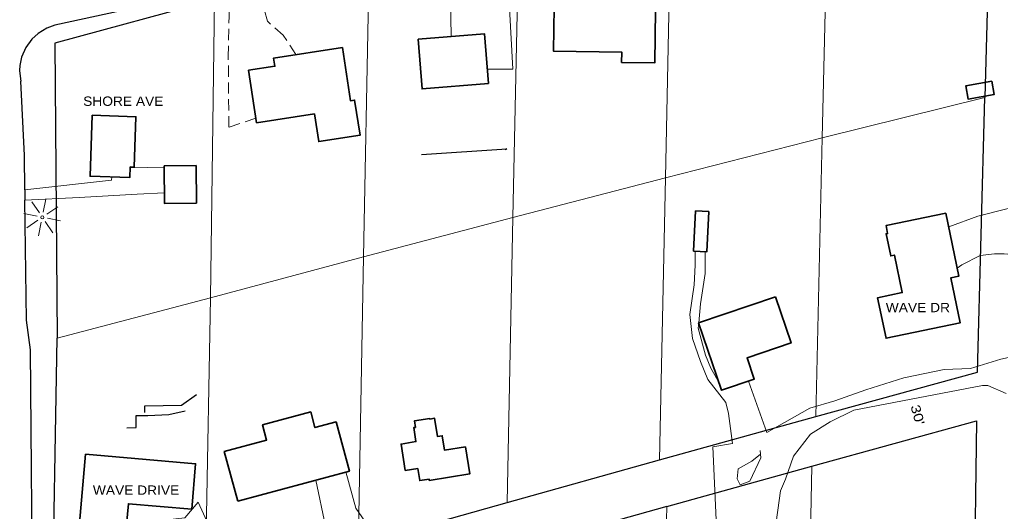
# Model space of a CAD drawing. Extents: x -861682 to -858969, y -1797841 to -1795153.
# Drawn here: x -860979 to -860350, y -1796083 to -1795768 of the extents above; entities that cross this region are included whole.
import ezdxf

# ---------------------------------------------------------------- set-up
doc = ezdxf.new("R2010")
doc.units = 0
doc.header["$LTSCALE"] = 2.4
doc.linetypes.add('MEDIUM_DASHED', pattern=[4.5, 3, -1.5])
for name, color, linetype, lineweight in [('10', 7, 'Continuous', 25), ('11', 7, 'Continuous', 13), ('12', 7, 'Continuous', 35), ('14', 7, 'Continuous', 25), ('17', 7, 'Continuous', 13), ('30', 7, 'Continuous', 13), ('42', 7, 'Continuous', 25), ('46', 7, 'Continuous', 13)]:
    doc.layers.add(name, color=color, linetype=linetype, lineweight=lineweight)
doc.layers.add('43', color=7, linetype='Continuous')

msp = doc.modelspace()

# ---------------------------------------------------------------- linework, layer by layer
at = {"layer": '10'}
for p, q in [((-860848.348, -1795747.62), (-860956.549, -1795771.257)), ((-860975.85, -1795876.828), (-860975.763, -1795883.427))]:
    msp.add_line(p, q, dxfattribs=at)
for points in [[(-860956.549, -1795771.257), (-860961.734, -1795773.101), (-860967.383, -1795776.511), (-860971.43, -1795780.239), (-860975.292, -1795785.589), (-860977.895, -1795791.653), (-860979.011, -1795797.041), (-860979.202, -1795800.339), (-860979.151, -1795802.184), (-860978.447, -1795807.129)], [(-860975.85, -1795876.828), (-860976.141, -1795854.84), (-860978.447, -1795807.129)], [(-860943.044, -1796154.171), (-860970.659, -1796157.721), (-860972.218, -1795979.333), (-860974.746, -1795960.452), (-860975.763, -1795883.427)]]:
    msp.add_lwpolyline(points, dxfattribs=at)
at = {"layer": '11'}
for p, q in [((-860702.361, -1795778.376), (-860703.253, -1795717.798)), ((-860886.521, -1795862.194), (-860908.271, -1795862.625)), ((-860504.025, -1796044.003), (-860503.778, -1796046.269))]:
    msp.add_line(p, q, dxfattribs=at)
for points in [[(-860679.135, -1795799.453), (-860662.826, -1795799.409), (-860664.822, -1795760.201), (-860679.57, -1795748.988), (-860683.051, -1795713.758)], [(-860920.125, -1795868.5), (-860920.237, -1795870.656), (-860975.85, -1795876.828)], [(-860886.377, -1795878.653), (-860903.856, -1795879.492), (-860940.935, -1795881.706), (-860975.763, -1795883.427)], [(-860382.998, -1795900.616), (-860364.271, -1795893.679), (-860344.937, -1795888.785), (-860335.906, -1795891.78)], [(-860545.785, -1795916.111), (-860545.707, -1795925.039), (-860546.305, -1795937.804), (-860549.216, -1795956.8), (-860547.423, -1795972.076), (-860542.331, -1795986.918), (-860537.504, -1795998.455), (-860526.033, -1796013.241), (-860524.246, -1796020.353), (-860521.787, -1796039.432), (-860534.291, -1796041.668), (-860531.924, -1796097.784)], [(-860539.402, -1795916.407), (-860539.28, -1795930.417), (-860542.231, -1795949.929), (-860543.384, -1795962.078), (-860543.72, -1795965.618), (-860539.024, -1795982.91), (-860535.703, -1795991.27), (-860530.382, -1796000.69)], [(-860377.503, -1795927.042), (-860374.63, -1795924.961), (-860362.868, -1795918.951), (-860353.662, -1795917.925), (-860347.518, -1795917.872), (-860345.154, -1795918.087), (-860338.779, -1795920.831)], [(-860511.432, -1795999.454), (-860499.637, -1796032.386), (-860472.127, -1796016.787), (-860456.099, -1796012.157), (-860436.312, -1796005.132), (-860411.805, -1795997.356), (-860385.86, -1795991.931), (-860369.088, -1795991.312), (-860349.527, -1795985.469), (-860344.775, -1795984.4)], [(-860494.603, -1796096.087), (-860491.039, -1796069.882), (-860487.797, -1796062.292), (-860482.727, -1796047.598), (-860471.744, -1796033.56), (-860459.053, -1796025.652), (-860443.995, -1796018.195), (-860361.431, -1796002.351), (-860357.886, -1796002.32), (-860346.068, -1796007.534)], [(-860789.227, -1796062.991), (-860782.902, -1796092.515), (-860782.148, -1796103.763)], [(-860769.837, -1796057.771), (-860763.391, -1796081.002), (-860753.902, -1796094.914)], [(-860917.073, -1796097.659), (-860916.785, -1796130.548), (-860908.966, -1796133.079), (-860898.837, -1796129.446), (-860896.275, -1796125.17), (-860887.561, -1796094.848), (-860886.433, -1796088.695), (-860873.214, -1796087.161), (-860864.558, -1796077.161), (-860857.812, -1796091.989), (-860857.779, -1796095.769), (-860865.264, -1796104.578), (-860866.128, -1796113.801), (-860866.241, -1796127.979), (-860864.349, -1796128.414)]]:
    msp.add_lwpolyline(points, dxfattribs=at)
at = {"layer": '11', "linetype": 'MEDIUM_DASHED'}
for points in [[(-860801.907, -1795790.043), (-860809.992, -1795777.538), (-860820.23, -1795768.648), (-860822.92, -1795758.274), (-860822.999, -1795749.296), (-860823.367, -1795742.164)], [(-860827.575, -1795830.845), (-860844.92, -1795836.68), (-860845.314, -1795791.551), (-860844.834, -1795765.319), (-860844.911, -1795756.576), (-860848.283, -1795749.281), (-860848.348, -1795747.62)]]:
    msp.add_lwpolyline(points, dxfattribs=at)
at = {"layer": '11'}
msp.add_lwpolyline([(-860503.778, -1796046.269), (-860509.4, -1796050.903), (-860518.101, -1796055.704), (-860518.754, -1796062.09), (-860516.828, -1796066.09), (-860510.706, -1796063.674), (-860503.511, -1796048.724)], close=True, dxfattribs=at)
at = {"layer": '12'}
for points in [[(-860636.235, -1795759.714), (-860601.024, -1795760.115), (-860600.841, -1795744.028), (-860570.928, -1795744.368), (-860571.507, -1795795.28), (-860592.912, -1795795.037), (-860592.837, -1795788.406), (-860636.554, -1795787.912)], [(-860723.486, -1795780.088), (-860680.983, -1795776.645), (-860678.396, -1795808.575), (-860720.899, -1795812.018)], [(-860772.116, -1795785.476), (-860816.244, -1795792.241), (-860815.429, -1795797.557), (-860832.283, -1795800.141), (-860827.126, -1795833.776), (-860790.015, -1795828.086), (-860787.287, -1795845.878), (-860760.76, -1795841.811), (-860764.227, -1795819.197), (-860766.887, -1795819.605)], [(-860355.339, -1795807.117), (-860372.09, -1795810.099), (-860370.579, -1795818.586), (-860353.828, -1795815.604)], [(-860932.653, -1795828.939), (-860904.526, -1795829.875), (-860905.602, -1795862.2), (-860908.254, -1795862.112), (-860908.479, -1795868.887), (-860933.952, -1795868.041)], [(-860886.528, -1795861.381), (-860865.972, -1795861.202), (-860865.762, -1795885.302), (-860886.318, -1795885.481)], [(-860545.538, -1795890.301), (-860546.731, -1795916.068), (-860538.208, -1795916.463), (-860537.014, -1795890.696)], [(-860384.846, -1795891.731), (-860376.459, -1795932.065), (-860381.629, -1795933.14), (-860375.619, -1795962.046), (-860423.27, -1795971.953), (-860428.664, -1795946.011), (-860412.863, -1795942.726), (-860417.867, -1795918.657), (-860420.25, -1795919.152), (-860423.188, -1795905.007), (-860422.211, -1795904.804), (-860423.269, -1795899.71)], [(-860494.254, -1795945.381), (-860543.493, -1795962.116), (-860528.797, -1796005.356), (-860507.809, -1795998.223), (-860512.454, -1795984.555), (-860484.203, -1795974.954)], [(-860839.281, -1796076.466), (-860767.616, -1796057.173), (-860776.109, -1796025.626), (-860789.711, -1796029.288), (-860792.423, -1796019.216), (-860823.303, -1796027.531), (-860820.679, -1796037.276), (-860847.862, -1796044.595)], [(-860731.702, -1796056.859), (-860734.45, -1796039.87), (-860724.858, -1796038.318), (-860726.314, -1796029.317), (-860725.187, -1796029.135), (-860725.857, -1796024.984), (-860716.055, -1796023.402), (-860715.983, -1796023.85), (-860712.894, -1796023.354), (-860711.021, -1796035.02), (-860707.981, -1796034.532), (-860706.482, -1796043.871), (-860693.16, -1796041.733), (-860690.395, -1796058.964), (-860716.384, -1796063.134), (-860716.514, -1796062.324), (-860722.448, -1796063.276), (-860723.684, -1796055.572)], [(-860941.194, -1796095.552), (-860936.898, -1796046.365), (-860866.253, -1796052.535), (-860868.798, -1796081.671), (-860909.433, -1796078.122), (-860911.184, -1796098.173)]]:
    msp.add_lwpolyline(points, close=True, dxfattribs=at)
at = {"layer": '14'}
for points in [[(-860721.422, -1795854.032), (-860666.633, -1795850.481), (-860667.585, -1795851.174)], [(-860898.824, -1796019.606), (-860898.889, -1796015.316), (-860875.263, -1796014.874), (-860865.633, -1796008.173)], [(-860910.403, -1796029.358), (-860904.437, -1796029.306), (-860904.506, -1796021.509), (-860896.945, -1796021.443), (-860883.481, -1796020.853), (-860872.867, -1796018.633)]]:
    msp.add_lwpolyline(points, dxfattribs=at)
at = {"layer": '17'}
for p, q in [((-860966.489, -1795891.538), (-860971.279, -1795884.41)), ((-860964.029, -1795891.078), (-860962.303, -1795882.678)), ((-860967.989, -1795893.738), (-860976.451, -1795892.064)), ((-860961.829, -1795892.478), (-860954.733, -1795887.738)), ((-860967.449, -1795896.238), (-860974.675, -1795901.094)), ((-860967.069, -1795906.198), (-860965.389, -1795897.598)), ((-860962.729, -1795897.138), (-860957.929, -1795904.352)), ((-860961.389, -1795894.998), (-860952.909, -1795896.722))]:
    msp.add_line(p, q, dxfattribs=at)
msp.add_circle((-860964.689, -1795894.438), 1, dxfattribs=at)
at = {"layer": '30'}
for p, q in [((-860460.096, -1795666.586), (-860464.207, -1795843.408)), ((-860560.934, -1795687.607), (-860564.854, -1795869.105)), ((-860658.826, -1795709.196), (-860662.655, -1795894.563)), ((-860754.869, -1795731.004), (-860758.477, -1795919.848)), ((-860854.119, -1795754.648), (-860856.81, -1795945.973)), ((-860359.939, -1795817.565), (-860464.207, -1795843.408)), ((-860468.3, -1796022.158), (-860464.207, -1795843.408)), ((-860568.645, -1796049.981), (-860564.854, -1795869.105)), ((-860666.261, -1796077.293), (-860662.655, -1795894.563)), ((-860761.9, -1796104.1), (-860758.477, -1795919.848)), ((-860955.102, -1795971.99), (-860856.81, -1795945.973)), ((-860860.091, -1796131.371), (-860856.81, -1795945.973)), ((-860470.949, -1796054.024), (-860477.624, -1796399.384)), ((-860570.941, -1796426.918), (-860563.945, -1796079.865))]:
    msp.add_line(p, q, dxfattribs=at)
msp.add_lwpolyline([(-860856.81, -1795945.973), (-860758.477, -1795919.848), (-860662.655, -1795894.563), (-860564.854, -1795869.105), (-860464.207, -1795843.408)], dxfattribs=at)
at = {"layer": '42'}
for p, q in [((-860568.645, -1796049.981), (-860468.3, -1796022.158)), ((-860666.261, -1796077.293), (-860568.645, -1796049.981)), ((-860563.945, -1796079.865), (-860470.949, -1796054.024)), ((-860761.9, -1796104.1), (-860666.261, -1796077.293)), ((-860563.945, -1796079.865), (-860663.246, -1796107.683))]:
    msp.add_line(p, q, dxfattribs=at)
for points in [[(-860560.934, -1795687.607), (-860355.195, -1795644.718), (-860359.939, -1795817.565)], [(-860854.119, -1795754.648), (-860956.515, -1795782.735), (-860955.102, -1795971.99)], [(-860468.3, -1796022.158), (-860364.648, -1795993.783), (-860359.939, -1795817.565)], [(-860860.091, -1796131.371), (-860958.277, -1796157.102), (-860955.102, -1795971.99)], [(-860470.949, -1796054.024), (-860365.3, -1796025.041), (-860369.736, -1796358.588), (-860477.624, -1796399.384)]]:
    msp.add_lwpolyline(points, dxfattribs=at)

# ---------------------------------------------------------------- texts
at = {"layer": '43', "width": 1.25}
msp.add_text("30'", height=6, rotation=285.342, dxfattribs=at).set_placement((-860407.577, -1796015.603))
at = {"layer": '46', "width": 1.1}
for s, p in [('SHORE AVE', (-860938.425, -1795822.927)), ('WAVE DR', (-860423.414, -1795955.281)), ('WAVE DRIVE', (-860932.192, -1796072.412))]:
    msp.add_text(s, height=6, dxfattribs=at).set_placement(p)

doc.saveas('drawing.dxf')
